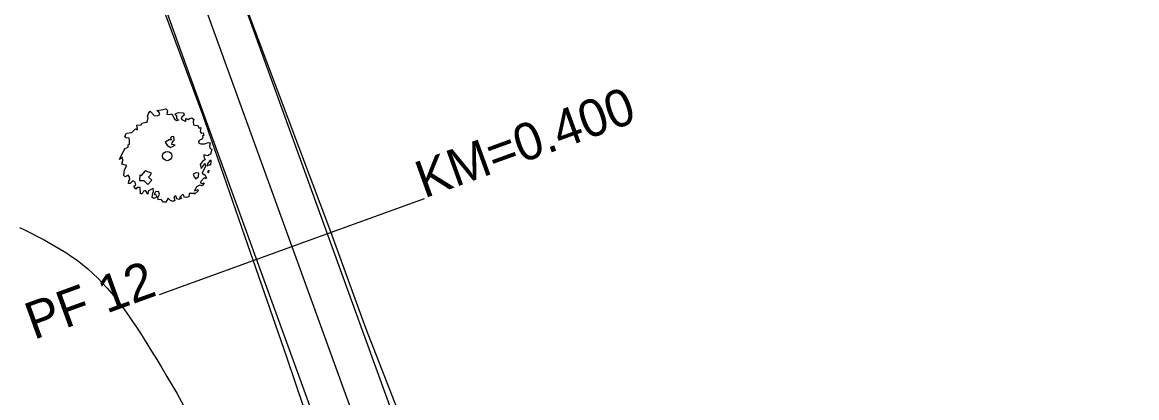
# Model space of a CAD drawing. Extents: x -475575 to -473225, y -1116053 to -1114104.
# Drawn here: x -474190.6 to -474131.3, y -1115125.1 to -1115105.1 of the extents above; entities that cross this region are included whole.
import ezdxf

# ---------------------------------------------------------------- set-up
doc = ezdxf.new("R2010")
doc.units = 0
for name, color, linetype in [('IP', 7, 'Continuous'), ('POLYGONY_SITUACE_PF', 7, 'Continuous'), ('POLYGONY_SITUACE_PF_POPISY', 7, 'Continuous'), ('POLYGONY_SITUACE_PO', 7, 'Continuous'), ('PopisPovrchu', 7, 'Continuous'), ('Vrstevnice_vedlejsi', 7, 'Continuous')]:
    doc.layers.add(name, color=color, linetype=linetype)

msp = doc.modelspace()

# ---------------------------------------------------------------- linework, layer by layer
at = {"layer": 'IP'}
for points in [[(-474180.917, -1115113.69), (-474181.031, -1115113.839), (-474181.16, -1115113.805), (-474181.336, -1115113.896), (-474181.432, -1115114.105), (-474181.261, -1115114.039), (-474181.237, -1115114.118), (-474181.431, -1115114.297), (-474181.419, -1115114.262), (-474181.715, -1115114.248), (-474181.736, -1115114.43), (-474181.865, -1115114.469), (-474181.983, -1115114.446), (-474182.008, -1115114.342), (-474182.078, -1115114.313), (-474182.231, -1115114.464), (-474182.107, -1115114.485), (-474182.25, -1115114.578), (-474182.384, -1115114.541), (-474182.434, -1115114.388), (-474182.528, -1115114.435), (-474182.486, -1115114.628), (-474182.58, -1115114.683), (-474182.716, -1115114.624), (-474182.829, -1115114.506), (-474182.958, -1115114.719), (-474183.08, -1115114.715), (-474183.21, -1115114.572), (-474183.365, -1115114.587), (-474183.389, -1115114.479), (-474183.297, -1115114.289), (-474183.346, -1115114.144), (-474183.505, -1115114.169), (-474183.589, -1115114.305), (-474183.505, -1115114.294), (-474183.468, -1115114.362), (-474183.449, -1115114.452), (-474183.602, -1115114.525), (-474183.691, -1115114.46), (-474183.661, -1115114.235), (-474183.611, -1115114.157), (-474183.638, -1115113.966), (-474183.646, -1115113.986), (-474183.894, -1115114.126), (-474183.916, -1115114.29), (-474184.038, -1115114.101), (-474184.159, -1115114.139), (-474184.215, -1115114.272), (-474184.313, -1115114.269), (-474184.329, -1115113.943), (-474184.489, -1115113.937), (-474184.567, -1115114.027), (-474184.66, -1115113.864), (-474184.559, -1115113.796), (-474184.591, -1115113.659), (-474184.714, -1115113.577), (-474184.862, -1115113.72), (-474184.949, -1115113.721), (-474184.929, -1115113.586), (-474184.883, -1115113.516), (-474184.888, -1115113.394), (-474184.971, -1115113.287), (-474185.13, -1115113.364), (-474185.191, -1115113.299), (-474185.158, -1115112.989), (-474185.036, -1115112.759), (-474185.306, -1115112.7), (-474185.251, -1115112.492), (-474185.268, -1115112.345), (-474185.436, -1115112.438), (-474185.137, -1115111.861), (-474184.975, -1115111.792), (-474184.969, -1115111.663), (-474184.894, -1115111.635), (-474184.89, -1115111.454), (-474184.917, -1115111.317), (-474185.074, -1115111.288), (-474185.144, -1115111.201), (-474185.064, -1115111.045), (-474184.78, -1115111.013), (-474184.578, -1115110.805), (-474184.467, -1115110.865), (-474184.511, -1115110.621), (-474184.266, -1115110.605), (-474184.239, -1115110.516), (-474184.015, -1115110.453), (-474183.962, -1115110.453), (-474183.899, -1115110.223), (-474183.938, -1115110.156), (-474183.879, -1115109.998), (-474183.799, -1115109.872), (-474183.589, -1115110.108), (-474183.422, -1115110.115), (-474183.279, -1115110.046), (-474183.314, -1115109.938), (-474183.442, -1115109.831), (-474183.203, -1115109.8), (-474182.956, -1115109.741), (-474182.87, -1115109.838), (-474182.911, -1115110.026), (-474182.787, -1115110.045), (-474182.636, -1115110.013), (-474182.503, -1115110.271), (-474182.389, -1115110.369), (-474182.294, -1115110.351), (-474182.371, -1115110.254), (-474182.371, -1115110.139), (-474182.456, -1115110.004), (-474182.281, -1115109.95), (-474182.028, -1115109.965), (-474181.98, -1115110.085), (-474182.101, -1115110.188), (-474182.141, -1115110.297), (-474181.93, -1115110.399), (-474181.894, -1115110.41), (-474181.892, -1115110.255), (-474181.774, -1115110.313), (-474181.701, -1115110.268), (-474181.571, -1115110.225), (-474181.469, -1115110.315), (-474181.513, -1115110.419), (-474181.496, -1115110.597), (-474181.357, -1115110.642), (-474181.272, -1115110.623), (-474181.184, -1115110.782), (-474181.09, -1115110.741), (-474181.133, -1115110.946), (-474181.082, -1115111.037), (-474180.977, -1115111.033), (-474180.932, -1115111.168), (-474181.002, -1115111.182), (-474180.996, -1115111.263), (-474181.022, -1115111.351), (-474181.06, -1115111.385), (-474181.127, -1115111.4), (-474181.187, -1115111.443), (-474181.228, -1115111.496), (-474181.204, -1115111.58), (-474181.105, -1115111.616), (-474180.884, -1115111.617), (-474180.714, -1115111.543), (-474180.61, -1115111.552), (-474180.64, -1115111.734), (-474180.596, -1115111.864), (-474180.517, -1115111.896), (-474180.579, -1115112.168), (-474180.647, -1115112.19), (-474180.742, -1115112.252), (-474180.939, -1115112.197), (-474180.947, -1115112.296), (-474180.859, -1115112.452), (-474181.017, -1115112.549), (-474181.127, -1115112.715), (-474181.084, -1115112.918), (-474180.861, -1115112.663), (-474180.849, -1115112.799), (-474181.026, -1115113.176), (-474180.891, -1115113.258), (-474180.791, -1115113.427), (-474180.812, -1115113.472), (-474180.915, -1115113.424), (-474181.119, -1115113.632), (-474181.075, -1115113.728)], [(-474182.646, -1115111.399), (-474182.789, -1115111.399), (-474182.991, -1115111.527), (-474182.894, -1115111.679), (-474182.719, -1115111.806), (-474182.459, -1115111.684), (-474182.635, -1115111.653), (-474182.617, -1115111.551), (-474182.547, -1115111.455), (-474182.517, -1115111.413), (-474182.54, -1115111.225), (-474182.634, -1115111.237), (-474182.71, -1115111.287), (-474182.68, -1115111.36)], [(-474180.626, -1115112.492), (-474180.739, -1115112.67), (-474180.753, -1115112.785), (-474180.599, -1115112.711), (-474180.575, -1115112.743), (-474180.54, -1115112.495)], [(-474183.73, -1115113.167), (-474184.058, -1115113.053), (-474184.299, -1115113.314), (-474184.352, -1115113.265), (-474184.359, -1115113.555), (-474184.139, -1115113.56), (-474183.917, -1115113.769), (-474183.709, -1115113.547), (-474183.878, -1115113.388), (-474183.78, -1115113.284)], [(-474181.206, -1115113.174), (-474181.363, -1115113.147), (-474181.513, -1115113.224), (-474181.461, -1115113.363), (-474181.357, -1115113.472), (-474181.22, -1115113.359)], [(-474180.659, -1115113.018), (-474180.738, -1115113.093), (-474180.701, -1115113.141), (-474180.666, -1115113.117)]]:
    msp.add_lwpolyline(points, close=True, dxfattribs=at)
msp.add_circle((-474182.886, -1115112.261), 0.247, dxfattribs=at)
at = {"layer": 'POLYGONY_SITUACE_PF'}
msp.add_lwpolyline([(-474183.299, -1115119.633), (-474176.248, -1115117.077), (-474169.198, -1115114.52)], dxfattribs=at)
at = {"layer": 'POLYGONY_SITUACE_PO'}
msp.add_lwpolyline([(-474033.93, -1115484.017), (-474028.81, -1115469.55), (-474027.706, -1115465.586), (-474027.155, -1115461.509), (-474027.167, -1115457.394), (-474027.702, -1115449.947), (-474028.133, -1115446.706), (-474028.952, -1115443.542), (-474030.148, -1115440.499), (-474155.776, -1115170.193), (-474159.336, -1115162.232), (-474162.663, -1115154.172), (-474165.754, -1115146.018), (-474287.504, -1114810.25), (-474291.915, -1114795.876)], dxfattribs=at)
at = {"layer": 'PopisPovrchu'}
for points in [[(-474181.118, -1115097.755), (-474174.845, -1115115.078), (-474170.533, -1115126.972), (-474166.798, -1115137.272), (-474162.997, -1115147.341), (-474159.197, -1115157.41), (-474153.963, -1115169.008), (-474147.951, -1115182.283), (-474140.426, -1115198.474), (-474132.457, -1115215.621)], [(-474132.257, -1115215.528), (-474133.541, -1115212.925), (-474140.108, -1115198.326), (-474146.676, -1115183.728), (-474150.655, -1115174.939), (-474152.662, -1115170.71), (-474155.776, -1115163.997), (-474158.891, -1115157.284), (-474161.951, -1115148.917), (-474165.011, -1115140.55), (-474170.196, -1115126.85), (-474172.318, -1115121.419), (-474174.179, -1115116.305), (-474178.153, -1115105.74), (-474181.118, -1115097.755)], [(-474136.084, -1115217.307), (-474143.442, -1115201.476), (-474150.8, -1115185.645), (-474153.819, -1115179.148), (-474156.839, -1115172.651), (-474159.866, -1115165.793), (-474162.894, -1115158.936), (-474166.097, -1115150.52), (-474169.3, -1115142.105), (-474170.559, -1115138.635), (-474175.745, -1115124.331), (-474180.931, -1115110.028), (-474181.982, -1115107.129), (-474183.034, -1115104.23), (-474183.96, -1115101.676), (-474184.886, -1115099.122)], [(-474185.046, -1115099.18), (-474181.011, -1115110.057), (-474178.771, -1115116.502), (-474176.531, -1115122.947), (-474174.667, -1115128.472), (-474171.947, -1115136.412), (-474169.827, -1115142.296), (-474166.54, -1115150.69), (-474163.254, -1115159.084), (-474160.346, -1115166.007), (-474157.438, -1115172.93), (-474153.022, -1115182.602), (-474151.43, -1115185.937), (-474144.518, -1115200.376), (-474136.354, -1115217.432)]]:
    msp.add_lwpolyline(points, dxfattribs=at)
at = {"layer": 'Vrstevnice_vedlejsi'}
for points in [[(-474106.724, -1115139.906), (-474105.975, -1115134.747), (-474104.91, -1115130.242), (-474103.528, -1115126.392), (-474101.829, -1115123.196), (-474101.248, -1115119.409), (-474101.786, -1115115.032), (-474103.442, -1115110.065), (-474106.201, -1115105.465), (-474110.065, -1115101.234), (-474115.032, -1115097.37), (-474120.595, -1115093.294), (-474126.753, -1115089.004), (-474133.506, -1115084.502), (-474139.856, -1115081.154), (-474145.801, -1115078.961), (-474151.342, -1115077.922), (-474155.382, -1115077.318), (-474157.922, -1115077.148), (-474158.961, -1115077.413), (-474159.927, -1115077.355), (-474160.82, -1115076.975), (-474161.64, -1115076.273), (-474163.375, -1115076.297), (-474166.027, -1115077.047), (-474169.593, -1115078.523), (-474174.953, -1115080.253), (-474182.107, -1115082.237), (-474191.053, -1115084.473), (-474198.277, -1115085.36), (-474203.777, -1115084.898), (-474207.554, -1115083.087), (-474210.582, -1115078.783), (-474212.862, -1115071.987), (-474214.394, -1115062.7), (-474215.425, -1115054.98), (-474215.955, -1115048.829), (-474215.985, -1115044.245), (-474215.583, -1115041.048), (-474214.749, -1115039.236), (-474213.484, -1115038.81), (-474212.393, -1115038.422), (-474211.477, -1115038.073), (-474210.736, -1115037.762), (-474210.235, -1115036.623), (-474209.974, -1115034.657), (-474209.953, -1115031.862), (-474210.087, -1115026.769), (-474210.376, -1115019.378), (-474210.819, -1115009.689), (-474212.181, -1114998.785), (-474214.462, -1114986.667), (-474217.662, -1114973.333), (-474220.697, -1114961.225), (-474223.567, -1114950.342), (-474226.271, -1114940.683), (-474228.65, -1114933.019), (-474230.705, -1114927.35), (-474232.434, -1114923.675), (-474233.1, -1114917.916), (-474232.704, -1114910.072), (-474231.244, -1114900.144), (-474229.766, -1114892.391), (-474228.27, -1114886.811), (-474226.756, -1114883.405), (-474225.554, -1114878.524), (-474224.663, -1114872.166), (-474224.082, -1114864.332), (-474222.871, -1114857.276), (-474221.027, -1114850.999), (-474218.553, -1114845.499), (-474216.392, -1114840.557), (-474214.547, -1114836.172), (-474213.015, -1114832.344), (-474210.719, -1114828.319), (-474207.656, -1114824.099), (-474203.828, -1114819.682), (-474200.394, -1114815.041), (-474197.354, -1114810.176), (-474194.708, -1114805.088), (-474192.13, -1114800), (-474189.62, -1114794.912), (-474187.178, -1114789.824), (-474182.801, -1114780.435), (-474176.49, -1114766.746), (-474168.245, -1114748.757), (-474162.295, -1114736.021), (-474158.639, -1114728.54), (-474157.277, -1114726.312), (-474156.001, -1114724.373), (-474154.81, -1114722.723), (-474153.704, -1114721.361), (-474151.414, -1114718.384), (-474147.941, -1114713.791), (-474143.284, -1114707.582), (-474139.388, -1114701.068), (-474136.252, -1114694.249)], [(-474190.746, -1115116.062), (-474187.399, -1115118.031), (-474183.721, -1115122.648), (-474179.711, -1115129.913), (-474175.37, -1115139.826), (-474172.214, -1115147.408), (-474170.243, -1115152.66), (-474169.457, -1115155.581), (-474169.433, -1115158.144), (-474170.172, -1115160.348), (-474171.674, -1115162.195), (-474174.12, -1115167.421), (-474177.509, -1115176.027), (-474181.841, -1115188.014), (-474186.266, -1115198.224), (-474190.783, -1115206.657), (-474195.391, -1115213.314), (-474199.546, -1115218.895), (-474203.248, -1115223.4), (-474206.496, -1115226.828), (-474209.248, -1115230.196), (-474211.503, -1115233.504), (-474213.262, -1115236.752), (-474215.625, -1115240.503), (-474218.59, -1115244.758), (-474222.158, -1115249.516), (-474226.123, -1115255.265), (-474230.484, -1115262.005), (-474235.242, -1115269.736), (-474238.679, -1115275.172), (-474240.794, -1115278.312), (-474241.589, -1115279.156), (-474246.298, -1115282.948), (-474254.922, -1115289.689), (-474267.461, -1115299.378), (-474278.075, -1115307.003), (-474286.765, -1115312.562), (-474293.53, -1115316.057), (-474300.274, -1115319.31), (-474306.995, -1115322.319), (-474313.695, -1115325.085), (-474320.564, -1115328.055), (-474327.601, -1115331.23), (-474334.807, -1115334.608), (-474341.419, -1115339.307), (-474347.436, -1115345.325), (-474352.86, -1115352.662), (-474356.666, -1115357.7), (-474358.856, -1115360.439), (-474359.428, -1115360.877), (-474363.116, -1115362.162), (-474369.919, -1115364.292), (-474379.838, -1115367.267), (-474387.589, -1115369.963), (-474393.171, -1115372.377), (-474396.586, -1115374.511), (-474400.976, -1115376.198), (-474406.341, -1115377.438), (-474412.682, -1115378.23), (-474419.24, -1115379.207), (-474426.015, -1115380.368), (-474433.008, -1115381.712), (-474439.797, -1115382.363), (-474446.384, -1115382.32), (-474452.769, -1115381.584), (-474459.341, -1115380.907), (-474466.102, -1115380.291), (-474473.051, -1115379.735), (-474479.251, -1115378.8), (-474484.701, -1115377.487), (-474489.402, -1115375.795), (-474495.413, -1115374.05), (-474502.735, -1115372.253), (-474511.367, -1115370.403), (-474520.449, -1115368.219), (-474529.978, -1115365.702), (-474539.957, -1115362.851), (-474547.727, -1115360.592), (-474553.29, -1115358.926), (-474556.645, -1115357.853), (-474562.53, -1115356.699), (-474570.946, -1115355.466), (-474581.892, -1115354.152), (-474589.986, -1115353.059), (-474595.226, -1115352.188), (-474597.613, -1115351.537), (-474603.649, -1115348.274), (-474613.333, -1115342.401), (-474626.667, -1115333.916), (-474636.193, -1115327.738), (-474641.912, -1115323.867), (-474643.824, -1115322.302), (-474645.574, -1115320.904), (-474647.162, -1115319.671), (-474648.588, -1115318.604), (-474652.255, -1115315.056), (-474658.163, -1115309.028)]]:
    msp.add_spline(points, degree=3, dxfattribs=at)

# ---------------------------------------------------------------- texts
at = {"layer": 'POLYGONY_SITUACE_PF_POPISY'}
for s, p in [('KM=0.400', (-474169.209, -1115114.524)), ('PF 12', (-474189.988, -1115122.059))]:
    msp.add_text(s, height=1.9765, rotation=19.93072, dxfattribs=at).set_placement(p)

doc.saveas('drawing.dxf')
